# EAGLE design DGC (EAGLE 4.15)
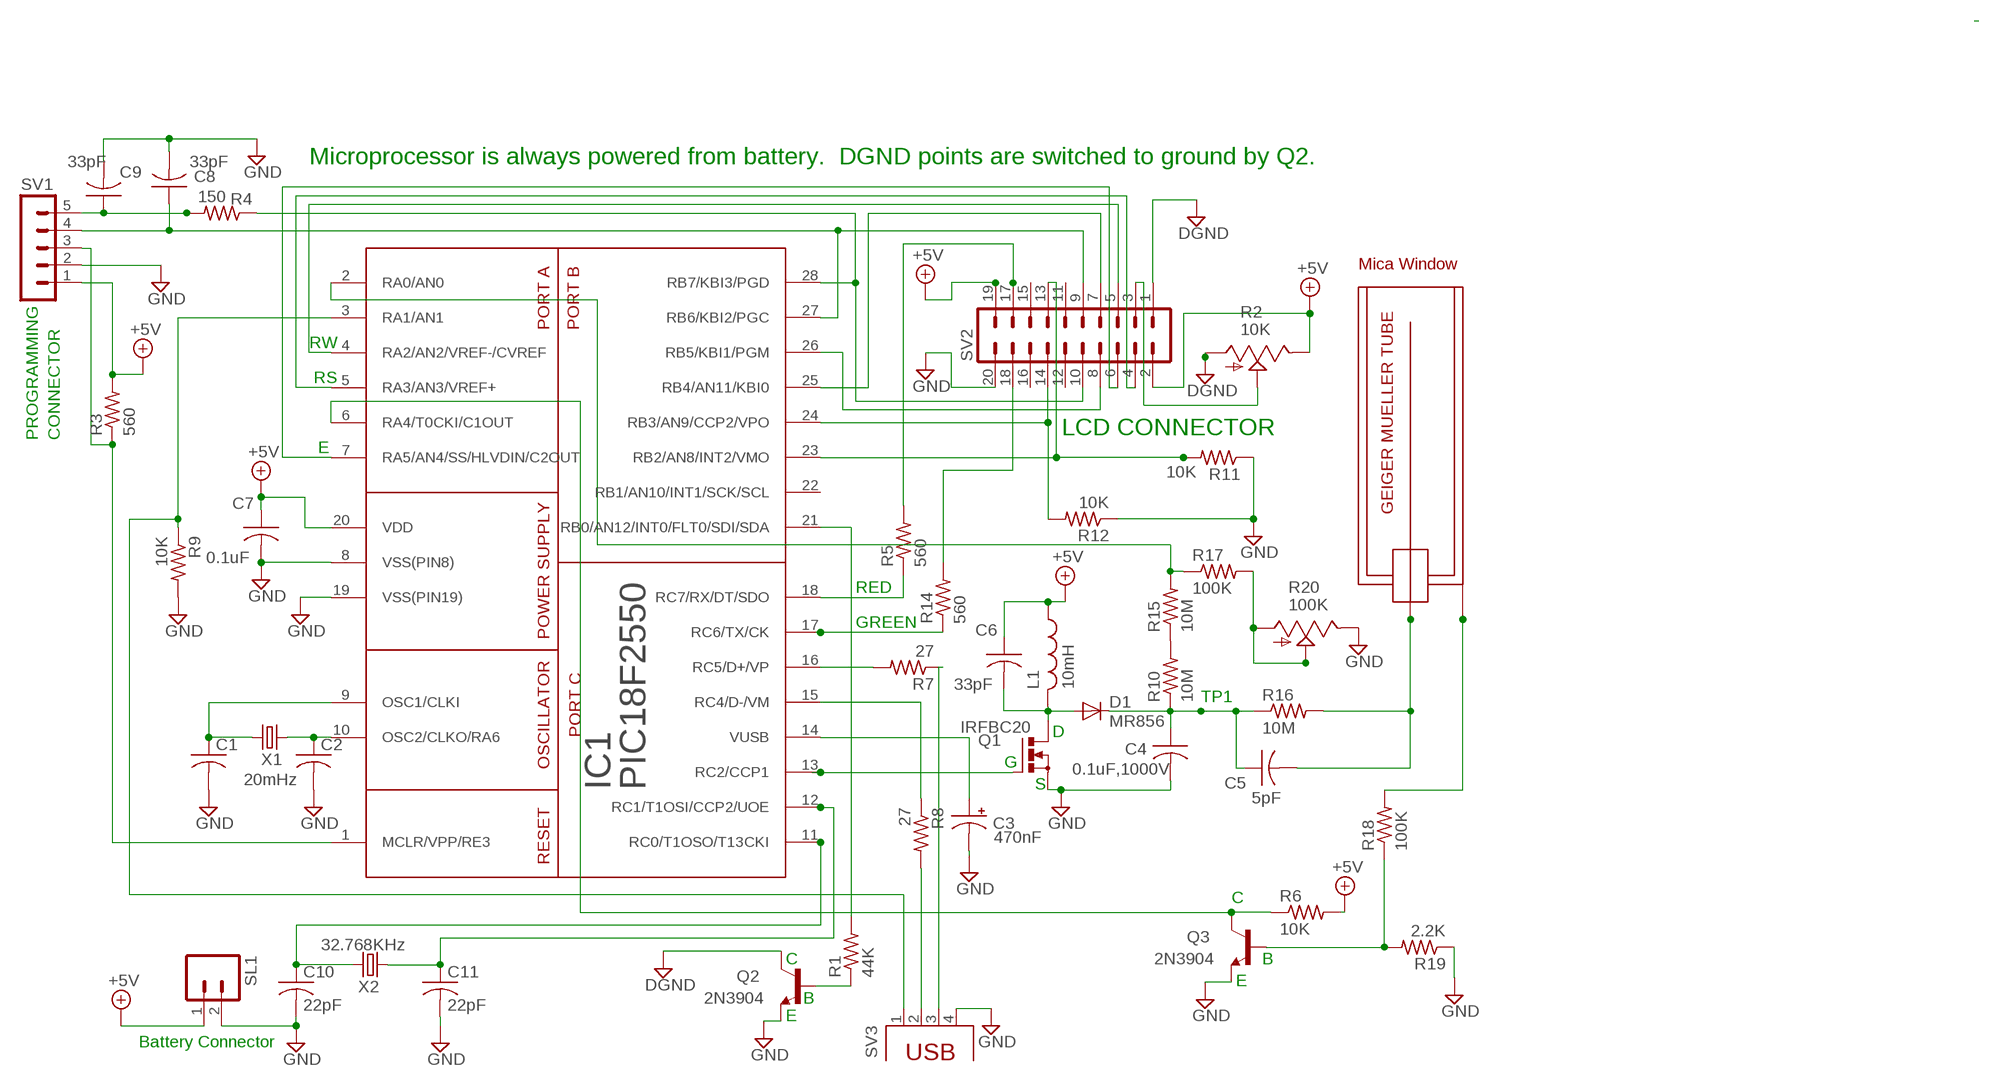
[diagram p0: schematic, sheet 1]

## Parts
C1  C-US025-025X050  [C025-025X050]
C2  C-US025-025X050  [C025-025X050]
C3  470nF  CPOL-USE2.5-5  [E2,5-5]
C4  0.1uF,1000V  C-US150-064X183  [C150-064X183]
C5  5pF  C-US050-030X075  [C050-030X075]
C6  33pF  C-US025-025X050  [C025-025X050]
C7  0.1uF  C-US025-025X050  [C025-025X050]
C8  33pF  C-US025-025X050  [C025-025X050]
C9  33pF  C-US025-025X050  [C025-025X050]
C10  22pF  C-US025-025X050  [C025-025X050]
C11  22pF  C-US025-025X050  [C025-025X050]
D1  MR856  1N5624  [DO201-15]
GM1  GM_TUBEGM  [GM_TUBE]
IC1  PIC18F2550  PIC18F2455SPDIP  [SPDIP-28]
L1  10mH  L-US0204/5  [0204/5]
Q1  IRFBC20  PMOSFET_NTO220BV  [TO220BV]
Q2  2N3904  [TO92]
Q3  2N3904  [TO92]
R1  44K  R-US_0309/10  [0309/10]
R2  10K  TRIM_US-B25X  [B25X]
R3  560  R-US_0309/V  [0309V]
R4  150  R-US_0309/10  [0309/10]
R5  560  R-US_0309/10  [0309/10]
R6  10K  R-US_0309/10  [0309/10]
R7  27  R-US_0309/10  [0309/10]
R8  27  R-US_0309/10  [0309/10]
R9  10K  R-US_0309/10  [0309/10]
R10  10M  R-US_0309/12  [0309/12]
R11  10K  R-US_0309/10  [0309/10]
R12  10K  R-US_0309/10  [0309/10]
R14  560  R-US_0309/10  [0309/10]
R15  10M  R-US_0309/12  [0309/12]
R16  10M  R-US_0309/12  [0309/12]
R17  100K  R-US_0309/12  [0309/12]
R18  100K  R-US_0309/12  [0309/12]
R19  2.2K  R-US_0309/12  [0309/12]
R20  100K  TRIM_US-B25X  [B25X]
SL1  M02  [02P]
SV1  MA05-1  [MA05-1]
SV2  MA10-2  [MA10-2]
SV3  PN61729  [PN61729]
X1  20mHz  CRYTALHC49U-V  [HC49U-V]
X2  32.768KHz  CRYTALTC26V  [TC26V]

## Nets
+5V: C6.1 C7.1 IC1.20(VDD) L1.1 R2.E R3.2 R6.2 SL1.1 SV1.1 SV2.2 SV2.19
DGND: Q2.1(C) R2.A SV2.1
GND: C1.2 C2.2 C3.- C4.2 C7.2 C8.2 C9.2 C10.2 C11.2 IC1.8(VSS(PIN8)) IC1.19(VSS(PIN19)) Q1.S Q2.3(E) Q3.3(E) R9.2 R11.1 R12.1 R19.1 R20.E SL1.2 SV1.2 SV2.20 SV3.4
N$1: C2.1 IC1.10(OSC2/CLKO/RA6) X1.2
N$2: C1.1 IC1.9(OSC1/CLKI) X1.1
N$3: IC1.28(RB7/KBI3/PGD) R4.1 SV2.10
N$4: IC1.1(MCLR/VPP/RE3) R3.1 SV1.3
N$5: C10.1 IC1.11(RC0/T1OSO/T13CKI) X2.2
N$6: IC1.25(RB4/AN11/KBI0) SV2.7
N$7: IC1.21(RB0/AN12/INT0/FLT0/SDI/SDA) R1.2
N$9: IC1.23(RB2/AN8/INT2/VMO) R11.2 SV2.13
N$10: IC1.24(RB3/AN9/CCP2/VPO) R12.2 SV2.14
N$11: IC1.7(RA5/AN4/SS/HLVDIN/C2OUT) SV2.6
N$12: IC1.6(RA4/T0CKI/C1OUT) Q3.1(C) R6.1
N$13: IC1.5(RA3/AN3/VREF+) SV2.4
N$14: R2.S SV2.3
N$15: C9.1 R4.2 SV1.5
N$16: IC1.13(RC2/CCP1) Q1.G
N$17: IC1.17(RC6/TX/CK) R14.1
N$19: IC1.18(RC7/RX/DT/SDO) R5.1
N$20: R5.2 SV2.17
N$21: R7.1 SV3.3
N$22: R10.2 R15.1
N$23: GM1.P$2 R18.2
N$24: C11.1 IC1.12(RC1/T1OSI/CCP2/UOE) X2.1
N$25: IC1.2(RA0/AN0) R15.2 R17.1
N$26: C3.+ IC1.14(VUSB)
N$27: R8.2 SV3.2
N$29: R17.2 R20.A R20.S
N$30: IC1.16(RC5/D+/VP) R7.2
N$31: IC1.15(RC4/D-/VM) R8.1
N$32: C6.2 D1.A L1.2 Q1.D
N$33: IC1.4(RA2/AN2/VREF-/CVREF) SV2.5
N$35: C5.2 GM1.P$1 R16.2
N$36: R14.2 SV2.18
N$37: C8.1 IC1.27(RB6/KBI2/PGC) SV1.4 SV2.9
N$40: Q3.2(B) R18.1 R19.2
N$43: C4.1 C5.1 D1.C R10.1 R16.1
N$47: Q2.2(B) R1.1
N$48: IC1.26(RB5/KBI1/PGM) SV2.8
N$49: IC1.3(RA1/AN1) R9.1 SV3.1
Unconnected: IC1.22(RB1/AN10/INT1/SCK/SCL) SV2.11 SV2.12 SV2.15 SV2.16

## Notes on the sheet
- Microprocessor is always powered from battery.  DGND points are switched to ground by Q2.
- RW
- RS
- LCD CONNECTOR
- PROGRAMMING | CONNECTOR
- E
- RED
- GREEN
- TP1
- D
- G
- S
- C
- C | B
- E
- B
- E
- Battery Connector

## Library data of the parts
C1 C2 C4-C11 = rcl:C-US: CAPACITOR, American symbol
C3 = rcl:CPOL-US: POLARIZED CAPACITOR, American symbol
D1 = diode:1N5624: DIODE
GM1 = gmtube:GM_TUBE
IC1 = pic18f2455:PIC18F2455
L1 = rcl:L-US: INDUCTOR, American symbol
Q1 = transistor-power:PMOSFET_N: Power MOSFET N-Channel
Q2 Q3 = transistor:2N3904: NPN TRANSISTOR
R1 R3-R12 R14-R19 = rcl:R-US_: RESISTOR, American symbol
R2 R20 = pot:TRIM_US-: POTENTIOMETER
SL1 = con-amp-quick:M02: AMP QUICK CONNECTOR
SV1 = con-lstb:MA05-1: PIN HEADER
SV2 = con-lstb:MA10-2: PIN HEADER
SV3 = con-berg:PN61729: BERG USB connector
X1 X2 = crystal:CRYTAL: CRYSTAL

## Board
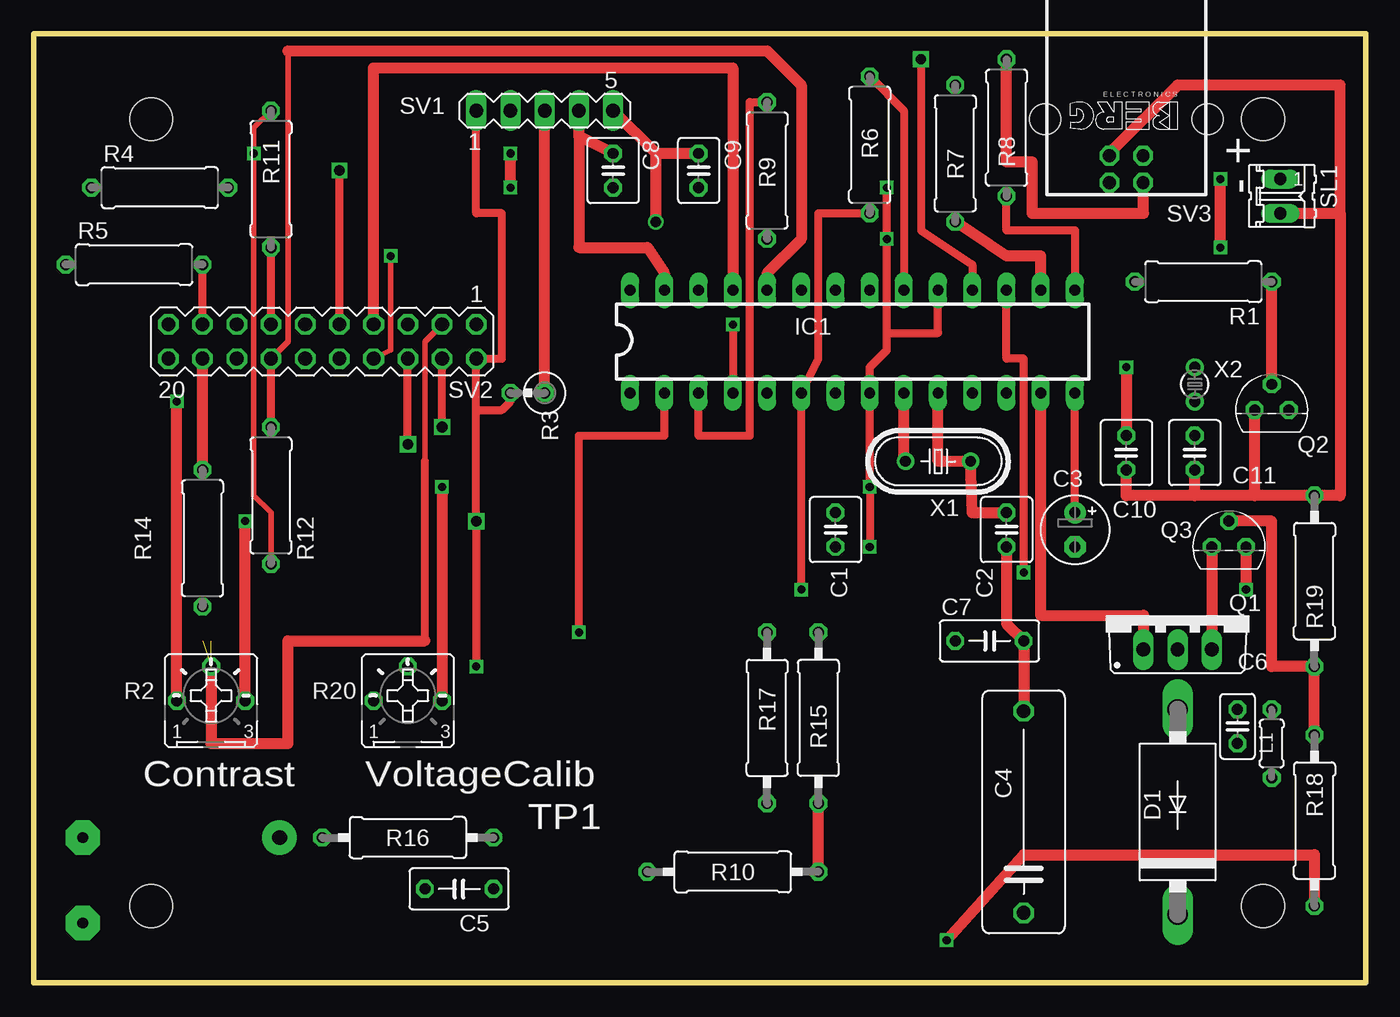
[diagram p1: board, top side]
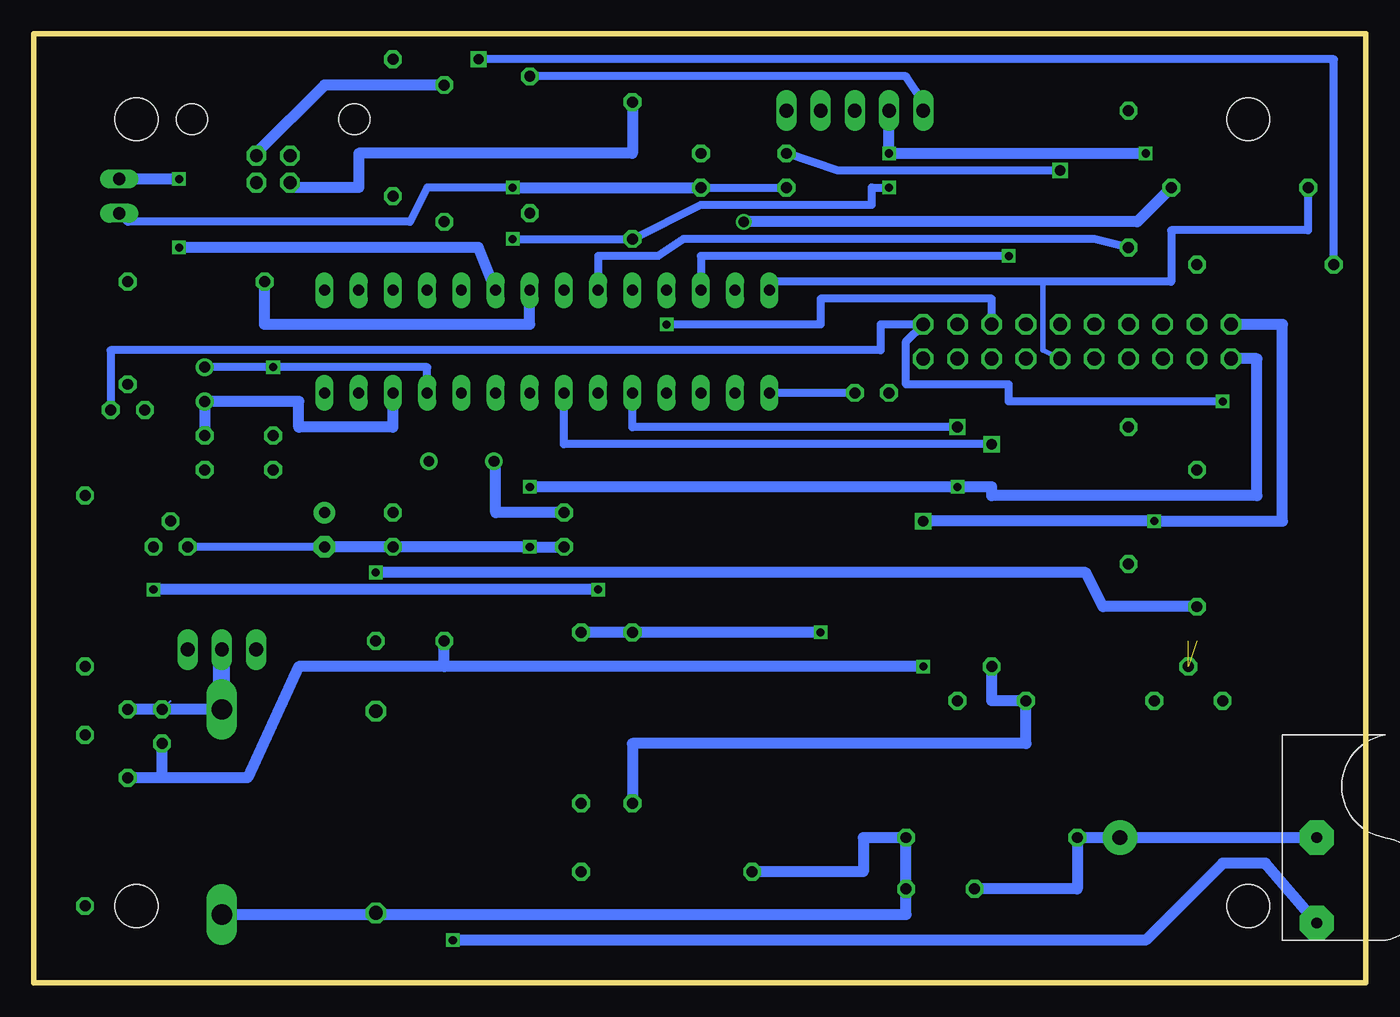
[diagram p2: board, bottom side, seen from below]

Size 98.89 x 70.48 mm. Coordinates in mm from the lower left corner, seen from the top.
Outline: 98.89,0.02 0,0.01 0,70.48 98.89,70.48
Outline: 98.89,70.48 98.89,0
Copper layers (1*16): Top 0.035mm / dielectric 1.5mm / Bottom 0.035mm
Design rules "default": minimum track width 5mil, minimum drill 23mil, track to track 8mil, track to pad 8mil, pad to pad 8mil, via to via 8mil, smd to smd 8mil, copper to edge 10mil, drill to drill 10mil, minimum pad ring 10mil, minimum via ring 8mil, stop-mask expansion 4mil, vias tented up to drill 0mil, thermal gap 10mil
Holes 3.2 mm at 8.73,64.14 8.73,5.71 91.27,5.71 91.27,64.14

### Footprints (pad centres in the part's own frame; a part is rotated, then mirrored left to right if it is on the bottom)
C025-040X050 = drill 0.813 octagon: 1 -1.27,0; 2 1.27,0
E2,5-5 = drill 0.813 pad 1.6 round: + -1.27,0 | drill 0.813 pad 1.6 octagon: - 1.27,0
C150-064X183 = drill 1.016 octagon: 1 -7.493,0; 2 7.493,0
C050-030X075 = drill 0.813 octagon: 1 -2.54,0; 2 2.54,0
C025-025X050 = drill 0.813 octagon: 1 -1.27,0; 2 1.27,0
C025-030X050 = drill 0.813 octagon: 1 -1.27,0; 2 1.27,0
DO201-15 = drill 1.499 long: A 7.62,0; C -7.62,0
GM_TUBE = drill 0.8 pad 2.54 octagon: P$1 0,0; P$2 6.35,0
SPDIP-28 = drill 0.813 long: 1 -3.81,16.51; 2 -3.81,13.97; 3 -3.81,11.43; 4 -3.81,8.89; 5 -3.81,6.35; 6 -3.81,3.81; 7 -3.81,1.27; 8 -3.81,-1.27; 9 -3.81,-3.81; 10 -3.81,-6.35; 11 -3.81,-8.89; 12 -3.81,-11.43; 13 -3.81,-13.97; 14 -3.81,-16.51; 15 3.81,-16.51; 16 3.81,-13.97; 17 3.81,-11.43; 18 3.81,-8.89; 19 3.81,-6.35; 20 3.81,-3.81; 21 3.81,-1.27; 22 3.81,1.27; 23 3.81,3.81; 24 3.81,6.35; 25 3.81,8.89; 26 3.81,11.43; 27 3.81,13.97; 28 3.81,16.51
0204/5 = drill 0.813 octagon: 1 -2.54,0; 2 2.54,0
TO220BV = drill 1.016 long: D 0,-2.54; G -2.54,-2.54; S 2.54,-2.54
TO92 = drill 0.813 octagon: 1 1.27,0; 2 0,1.905; 3 -1.27,0
0309/10 = drill 0.813 octagon: 1 -5.08,0; 2 5.08,0
B25P = drill 0.813 octagon: A -2.54,0; E 2.54,0; S 0,2.54
0309V = drill 0.813 octagon: 1 -1.27,0; 2 1.27,0
0309/12 = drill 0.813 octagon: 1 -6.35,0; 2 6.35,0
02P = drill 0.914 long: 1 -1.27,0; 2 1.27,0
MA05-1 = drill 1.016 long: 1 -5.08,0; 2 -2.54,0; 3 0,0; 4 2.54,0; 5 5.08,0
MA10-2 = drill 1.016 octagon: 1 -11.43,-1.27; 2 -11.43,1.27; 3 -8.89,-1.27; 4 -8.89,1.27; 5 -6.35,-1.27; 6 -6.35,1.27; 7 -3.81,-1.27; 8 -3.81,1.27; 9 -1.27,-1.27; 10 -1.27,1.27; 11 1.27,-1.27; 12 1.27,1.27; 13 3.81,-1.27; 14 3.81,1.27; 15 6.35,-1.27; 16 6.35,1.27; 17 8.89,-1.27; 18 8.89,1.27; 19 11.43,-1.27; 20 11.43,1.27
PN61729 = drill 0.95 octagon: 1 1.25,4.71; 2 -1.25,4.71; 3 -1.25,2.71; 4 1.25,2.71 | hole 2.3: -6.02,0; 6.02,0
HC49U-V = drill 0.813 round: 1 -2.413,0; 2 2.413,0
TC26V = drill 0.813 round: 1 -1.27,0; 2 1.27,0

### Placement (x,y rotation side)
C1  [C025-040X050]  59.52,33.66 270 top
C2  [C025-040X050]  72.22,33.66 270 top
C3  77.3,33.66 270 top
C4  73.49,12.7 90 top
C5  31.59,6.98 180 top
C6  89.37,19.05 90 top
C7  0.1uF  [C050-030X075]  70.95,25.4 0 top
C8  33pF  [C025-040X050]  43.02,60.32 270 top
C9  33pF  [C025-030X050]  49.37,60.32 270 top
C10  22pF  [C025-040X050]  81.11,39.37 270 top
C11  22pF  [C025-040X050]  86.19,39.37 270 top
D1  84.92,12.7 90 top
GM1  3.65,10.79 270 bottom
IC1  60.8,47.62 90 top
L1  91.91,17.78 90 top
Q1  84.92,27.31 0 top
Q2  91.91,42.54 0 top
Q3  88.73,32.38 0 top
R1  86.83,52.07 180 top
R2  10K  [B25P]  13.17,20.96 0 top
R3  36.66,43.81 180 top
R4  9.36,59.05 0 top
R5  7.46,53.34 0 top
R6  62.06,62.23 90 top
R7  68.41,61.59 270 top
R8  72.22,63.5 90 top
R9  54.45,60.32 270 top
R10  51.91,8.26 0 top
R11  17.62,59.69 270 top
R12  17.62,36.2 90 top
R14  12.54,33.02 90 top
R15  58.26,19.69 90 top
R16  27.78,10.79 180 top
R17  54.45,19.69 270 top
R18  95.08,12.06 270 top
R19  95.08,29.85 270 top
R20  100K  [B25P]  27.78,20.96 0 top
SL1  92.54,58.42 270 top
SV1  37.94,64.77 0 top
SV2  21.43,47.62 180 top
SV3  81.11,64.14 180 top
X1  67.14,38.73 0 top
X2  86.19,44.45 90 top

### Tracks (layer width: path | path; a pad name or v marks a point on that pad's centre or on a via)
+5V  (via drill 0.6, 0.8)
  Top 0.61: IC1.20 64.6,64.77 R6.2 | SV1.1 32.86,57.15 34.76,57.15 34.76,46.35 SV2.2 32.86,42.54 | R3.2 35.4,43.18 34.76,42.54 32.86,42.54 | 32.86,42.54 v32.86,34.29 v32.86,23.5
  Top 0.813: v88.1,54.61 v88.1,59.69 | R2.E v15.71,34.29
  Bottom 0.127: SV1.1 32.86,65.41
  Bottom 0.61: R6.2 34.12,67.31 32.86,65.41
  Bottom 0.813: v88.1,59.69 SL1.1 | v88.1,54.61 65.88,54.61 IC1.20 | 89.37,15.24 L1.1 | 89.37,15.24 C6.1 | 89.37,15.24 83.02,15.24 79.21,23.5 68.41,23.5 | 68.41,23.5 C7.1 | v32.86,23.5 68.41,23.5 | SV2.19 6.18,48.89 6.18,34.29 v15.71,34.29 v32.86,34.29
DGND  (via drill 0.6)
  Top 0.813: R2.A v10.63,43.18
  Bottom 0.61: v10.63,43.18 26.51,43.18 26.51,44.45 34.12,44.45 34.12,47.62 SV2.1 36.03,48.89 36.03,46.99 93.18,46.99 Q2.1
GND  (via drill 0.6)
  Top 0.127: 79.84,61.59 SV3.4 | 73.49,19.69 C4.2 73.49,20.32
  Top 0.406: R12.1 17.62,34.92 16.35,36.2 v16.35,61.59 16.35,63.5 R11.1 | v63.34,55.24 63.34,52.7
  Top 0.61: 96.99,36.2 R19.1 | v63.34,59.05 v63.34,55.24 63.34,48.26 | 63.34,48.26 63.34,46.99 62.06,45.72 IC1.8 v62.06,36.83 v62.06,32.38 | IC1.19 67.14,48.26 63.34,48.26
  Top 0.813: C10.2 81.11,36.2 86.19,36.2 | 86.19,36.2 C11.2 | 90.64,36.2 86.19,36.2 | 90.64,36.2 Q2.3 | 79.84,61.59 84.92,66.68 96.99,66.68 96.99,57.15 | 90.64,36.2 96.99,36.2 96.99,57.15 | v35.4,59.05 v35.4,61.59 | SL1.2 96.99,57.15 | Q3.3 Q1.S | 73.49,20.32 C7.2 72.22,26.67 C2.2 | v30.32,36.83 R20.E
  Bottom 0.61: v35.4,59.05 36.66,59.05 36.66,57.78 49.37,57.78 R9.2 v63.34,55.24 | SL1.2 91.91,56.52 70.95,56.52 69.68,59.05 v63.34,59.05 | C9.2 C8.2 | C3.- Q3.3
  Bottom 0.813: SV1.2 v35.4,61.59 v16.35,61.59 | v63.34,59.05 C9.2 | C3.- C2.2 v62.06,32.38 C1.2 | v62.06,36.83 v30.32,36.83 27.78,36.83 27.78,36.2 8.09,36.2 8.09,46.35 SV2.20
N$1
  Top 0.813: IC1.10 67.14,38.73 X1.2 69.68,34.92 C2.1
N$2
  Top 0.406: X1.1 64.6,38.73
  Top 0.813: 64.6,38.73 IC1.9
  Bottom 0.406: 64.6,38.73 X1.1
  Bottom 0.813: 64.6,38.73 64.6,34.92 C1.1
N$3
  Bottom 0.406: SV2.10 23.96,46.99 23.96,52.07
  Bottom 0.61: IC1.28 44.29,52.07 23.96,52.07 14.44,52.07 14.44,55.88 4.28,55.88 R4.1
N$4
  Top 0.813: R3.1 SV1.3
  Bottom 0.61: R3.1 IC1.1
N$5  (via drill 0.6)
  Top 0.813: v81.11,45.72 C10.1
  Bottom 0.61: X2.2 v81.11,45.72 69.68,45.72 IC1.11
N$6
  Top 0.813: IC1.25 51.91,67.95 25.23,67.95 SV2.7
N$7
  Bottom 0.813: IC1.21 62.06,48.89 81.75,48.89 R1.2
N$9
  Top 0.61: SV2.13 R11.2
  Bottom 0.61: R11.2 20.16,55.24 50.63,55.24 52.54,53.98 56.98,53.98 IC1.23
N$10
  Top 0.406: 18.89,49.53 18.89,69.22 | 18.89,49.53 18.89,47.62 SV2.14 | 18.89,49.53 18.89,50.16
  Top 0.61: R12.2 SV2.14
  Top 0.813: 18.89,69.22 54.45,69.22 56.98,66.68 56.98,55.24 54.45,52.7 IC1.24
N$11  (via drill 0.8)
  Top 0.61: v27.78,40 SV2.6
  Bottom 0.61: IC1.7 59.52,40 v27.78,40
N$12  (via drill 0.6)
  Top 0.61: R6.1 58.26,57.15 58.26,46.35 IC1.6 v56.98,29.21
  Top 0.813: v90,29.21 Q3.1
  Bottom 0.813: v56.98,29.21 v90,29.21
N$13  (via drill 0.8)
  Top 0.61: v30.32,41.27 SV2.4
  Bottom 0.61: v30.32,41.27 54.45,41.27 IC1.5
N$14  (3 unrouted)
  Top 0.406: 29.05,38.73 29.05,47.62 SV2.3
  Top 0.61: 29.05,25.4 29.05,38.73
  Top 0.813: R2.S 13.17,17.78 18.89,17.78 18.89,25.4 29.05,25.4
N$15  (via drill 0.76)
  Top 0.813: v46.19,56.52 46.19,61.59 | 46.19,61.59 SV1.5 | 46.19,61.59 C9.1
  Bottom 0.813: R4.2 16.98,56.52 v46.19,56.52
N$16
  Top 0.813: IC1.13 74.77,27.31 82.38,27.31 Q1.G
N$17  (via drill 0.6)
  Top 0.61: v73.49,30.48 73.49,46.35 72.22,46.35 IC1.17
  Bottom 0.813: R14.1 19.52,27.94 20.79,30.48 v73.49,30.48
N$19  (via drill 0.76)
  Top 0.61: v65.88,68.58 65.88,55.88 69.68,53.34 IC1.18
  Bottom 0.61: v65.88,68.58 2.38,68.58 R5.1
N$20
  Top 0.61: SV2.17 R5.2
N$21
  Bottom 0.127: 82.38,61.59 SV3.3
  Bottom 0.813: R7.1 77.3,66.68 82.38,61.59
N$22
  Top 0.813: R10.2 R15.1
N$23  (via drill 0.6)
  Top 0.813: R18.2 95.08,9.53 73.49,9.53 v67.78,3.17
  Bottom 0.813: v67.78,3.17 16.35,3.17 10.63,8.89 7.46,8.89 GM1.P$2 3.01,4.45
N$24
  Bottom 0.813: IC1.12 72.22,41.27 79.21,41.27 79.21,43.18 X2.1 86.19,41.91 C11.1
N$25  (via drill 0.6)
  Top 0.61: v40.48,26.04 40.48,40.64 46.83,40.64 IC1.2
  Bottom 0.813: R15.2 R17.1 v40.48,26.04
N$26
  Top 0.61: C3.+ IC1.14
N$27
  Top 0.61: 82.38,59.05 SV3.2
  Top 0.813: R8.2 72.22,60.96 74.13,60.96 74.13,57.15 82.38,57.15 82.38,59.05 82.38,59.69
N$29
  Bottom 0.813: R20.S 27.78,20.96 R20.A 25.23,17.78 54.45,17.78 R17.2
N$30
  Top 0.813: IC1.16 74.77,53.98 72.22,53.98 R7.2
N$31
  Top 0.61: R8.1 72.22,55.88 77.3,55.88 IC1.15
N$32
  Bottom 0.127: C6.2 88.73,20.96
  Bottom 0.813: D1.A C6.2 L1.2
  Bottom 1.27: D1.A Q1.D
N$33  (via drill 0.6)
  Top 0.61: v51.91,48.89 IC1.4
  Bottom 0.61: SV2.5 27.78,50.8 40.48,50.8 40.48,48.89 v51.91,48.89
N$35  (via drill 1.1 pad 2.54)
  Bottom 0.813: C5.2 21.43,6.98 R16.2 v18.25,10.79 GM1.P$1
N$36
  Top 0.813: R14.2 SV2.18
N$37  (via drill 0.76)
  Top 0.61: SV2.9 v22.7,60.32
  Top 0.813: 40.48,62.86 40.48,54.61 45.55,54.61 46.83,52.7 IC1.27 | 40.48,62.86 SV1.4 | C8.1 40.48,62.86
  Bottom 0.61: v22.7,60.32 39.2,60.32 C8.1
N$40
  Top 0.813: R18.1 R19.2 91.91,23.5 91.91,34.29 Q3.2
N$43
  Bottom 0.61: 73.49,5.08 C4.1
  Bottom 0.813: D1.C 73.49,5.08 34.12,5.08 C5.1 R16.1 37.3,10.79 37.3,8.26 R10.1
N$47
  Top 0.813: Q2.2 R1.1
N$48  (via drill 0.6)
  Top 0.406: SV2.8 26.51,46.99 v26.51,53.98
  Bottom 0.127: IC1.26 49.37,52.7
  Bottom 0.61: v26.51,53.98 49.37,53.98 IC1.26
N$49
  Top 0.61: R9.1 53.18,65.41 53.18,40.64 49.37,40.64 IC1.3
  Bottom 0.127: 79.84,59.05 SV3.1
  Bottom 0.61: 79.84,59.05 79.84,59.69
  Bottom 0.813: 79.84,59.05 74.77,59.05 74.77,61.59 54.45,61.59 R9.1

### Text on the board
tNames: - + | Contrast | VoltageCalib | TP1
